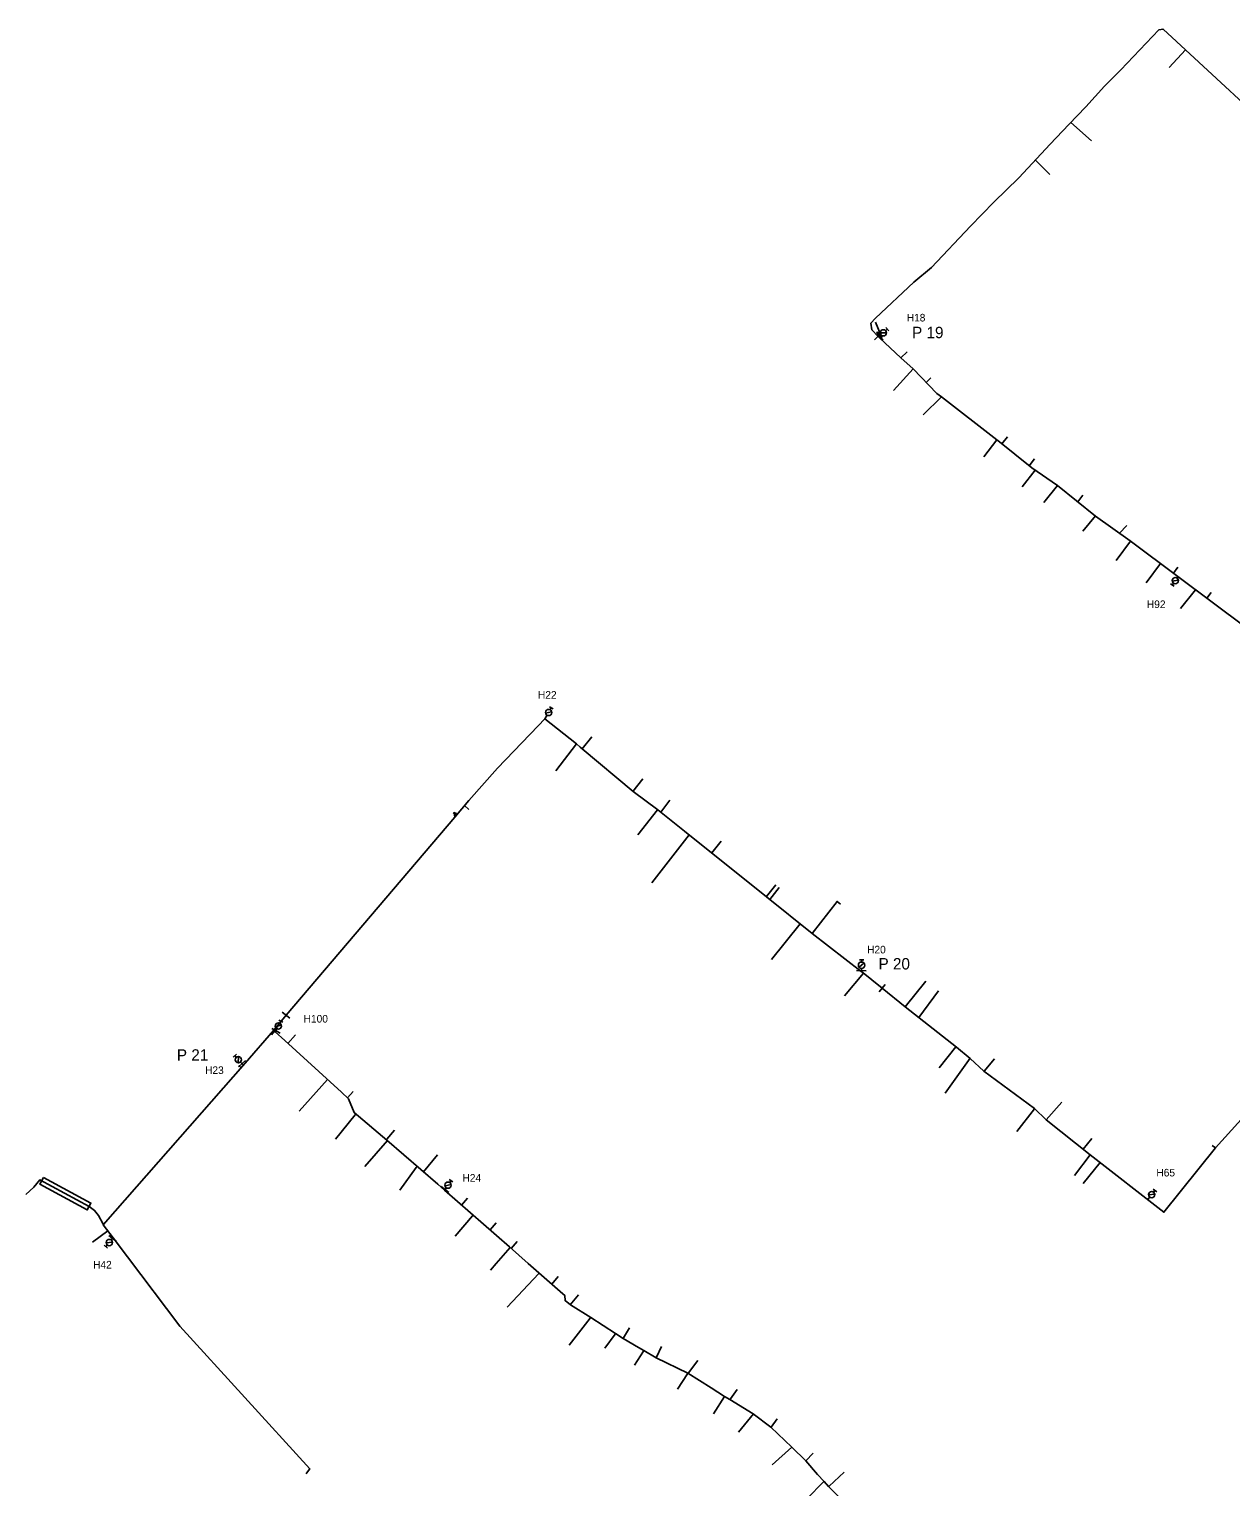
# Model space of a CAD drawing. Extents: x -548873 to -538270, y -1201997 to -1192514.
# Drawn here: x -547630.3 to -547314.4, y -1195490.5 to -1195107.4 of the extents above; entities that cross this region are included whole.
import ezdxf

# ---------------------------------------------------------------- set-up
doc = ezdxf.new("R2010")
doc.units = 0
for name, color, linetype in [('KN_HRAN_STÁTNÍ', 7, 'Continuous'), ('KN_PARC_Č', 7, 'Continuous'), ('KN_VKP_HRAN_SPORNÁ', 7, 'Continuous'), ('PK_PARC_Čv', 7, 'Continuous'), ('Vrstva 29', 7, 'Continuous'), ('Vrstva 37', 7, 'Continuous'), ('Vrstva 39', 7, 'Continuous')]:
    doc.layers.add(name, color=color, linetype=linetype)

# ---------------------------------------------------------------- blocks, each defined once
blk = doc.blocks.new('147')
at = {"layer": 'KN_HRAN_STÁTNÍ'}
blk.add_line((0, 1.27), (0, -1.27), dxfattribs=at)
blk = doc.blocks.new('160')
at = {"layer": 'KN_HRAN_STÁTNÍ'}
blk.add_circle((0, 0), 0.0458, dxfattribs=at)
blk = doc.blocks.new('133')
at = {"layer": 'KN_HRAN_STÁTNÍ'}
for p, q in [((0.28, 0), (0, 0)), ((0.54, 0.58), (1.7, -0.58)), ((1.94, 0), (2.52, 0)), ((2.52, 0.58), (2.52, -0.58))]:
    blk.add_line(p, q, dxfattribs=at)
blk.add_circle((1.11, 0), 0.825, dxfattribs=at)
blk = doc.blocks.new('150')
at = {"layer": 'KN_HRAN_STÁTNÍ'}
blk.add_line((0, 1.27), (0, -1.27), dxfattribs=at)
blk = doc.blocks.new('128')
at = {"layer": 'KN_HRAN_STÁTNÍ'}
for p, q in [((-0.19, 1.06), (-0.43, 1.15)), ((-0.36, 0.84), (-0.19, 1.06)), ((-0.19, 1.06), (-0.02, 1.25)), ((-0.19, 1.06), (0, 0)), ((0.05, 0.95), (-0.19, 1.06)), ((-0.1, 1), (0.41, 0.91)), ((-0.07, 0.82), (0.17, 0.96)), ((0.17, 0.96), (-0.02, 1.13)), ((0.17, 0.96), (0, 0)), ((0.19, 1.21), (0.17, 0.96)), ((0.17, 0.96), (0.38, 1.08)), ((0.36, 0.77), (0.17, 0.96))]:
    blk.add_line(p, q, dxfattribs=at)

msp = doc.modelspace()

# ---------------------------------------------------------------- linework, layer by layer
at = {"layer": 'KN_PARC_Č'}
for points in [[(-547326.381, -1195112.848), (-547330.603, -1195117.527)], [(-547356.485, -1195131.963), (-547351.024, -1195136.804)], [(-547365.802, -1195141.849), (-547362.026, -1195145.627)], [(-547406.503, -1195188.856), (-547406.204, -1195188.492), (-547407.816, -1195184.471)], [(-547401.169, -1195193.786), (-547399.552, -1195192.239)], [(-547397.94, -1195196.725), (-547403.117, -1195202.407)], [(-547394.499, -1195200.278), (-547393.258, -1195199.076)], [(-547390.528, -1195204.113), (-547395.281, -1195208.834)], [(-547374.589, -1195216.412), (-547373.141, -1195214.62)], [(-547375.92, -1195215.349), (-547379.378, -1195219.882)], [(-547367.442, -1195222.166), (-547366.066, -1195220.38)], [(-547365.896, -1195223.313), (-547369.293, -1195227.711)], [(-547360.023, -1195227.352), (-547363.601, -1195231.869)], [(-547354.654, -1195231.656), (-547353.304, -1195229.914)], [(-547350.034, -1195235.36), (-547353.34, -1195239.37)], [(-547343.707, -1195239.893), (-547341.79, -1195237.86)], [(-547340.766, -1195242.001), (-547344.538, -1195247.058)], [(-547332.901, -1195247.876), (-547336.664, -1195252.934)], [(-547329.512, -1195250.407), (-547328.359, -1195248.873)], [(-547323.68, -1195254.763), (-547327.616, -1195259.664)], [(-547320.739, -1195256.96), (-547319.611, -1195255.461)], [(-547486.476, -1195295.298), (-547491.912, -1195302.375)], [(-547484.932, -1195296.547), (-547482.387, -1195293.385)], [(-547471.616, -1195307.744), (-547468.977, -1195304.494)], [(-547464.251, -1195313.246), (-547461.899, -1195310.091)], [(-547515.868, -1195311.487), (-547514.738, -1195312.474)], [(-547465.106, -1195312.565), (-547470.324, -1195319.21)], [(-547456.856, -1195319.155), (-547466.648, -1195331.809)], [(-547450.889, -1195323.923), (-547448.427, -1195320.847)], [(-547436.5, -1195335.421), (-547434.057, -1195332.279)], [(-547435.601, -1195336.144), (-547433.173, -1195332.992)], [(-547424.512, -1195345.067), (-547417.918, -1195336.689), (-547417.001, -1195337.424)], [(-547427.641, -1195342.55), (-547435.139, -1195351.919)], [(-547411.032, -1195355.484), (-547416.015, -1195361.46)], [(-547400.069, -1195364.357), (-547394.573, -1195357.586)], [(-547396.459, -1195367.202), (-547391.313, -1195360.133)], [(-547562.328, -1195373.977), (-547560.319, -1195371.765)], [(-547386.678, -1195374.91), (-547391.075, -1195380.4)], [(-547382.968, -1195377.872), (-547389.56, -1195387.054)], [(-547379.306, -1195381.295), (-547376.549, -1195378.035)], [(-547574.578, -1195380.387), (-547575.215, -1195379.795)], [(-547551.867, -1195383.499), (-547559.371, -1195391.76)], [(-547546.629, -1195388.267), (-547545.111, -1195386.6)], [(-547366.008, -1195391.159), (-547370.716, -1195397.158)], [(-547362.966, -1195394.05), (-547358.836, -1195389.461)], [(-547544.462, -1195392.486), (-547544.66, -1195392.72), (-547549.822, -1195399.133)], [(-547536.403, -1195399.288), (-547536.32, -1195399.19), (-547534.291, -1195396.783)], [(-547536.165, -1195399.492), (-547542.121, -1195406.33)], [(-547353.25, -1195401.75), (-547350.994, -1195398.962)], [(-547318.463, -1195401.456), (-547319.335, -1195400.785)], [(-547528.326, -1195406.29), (-547528.56, -1195406.56), (-547532.845, -1195412.576)], [(-547526.671, -1195407.725), (-547523.002, -1195403.252)], [(-547351.384, -1195403.229), (-547355.534, -1195408.716)], [(-547348.788, -1195405.252), (-547353.278, -1195410.771)], [(-547610.869, -1195421.66), (-547610.98, -1195421.31), (-547612.09, -1195419.18), (-547613.15, -1195417.89), (-547614.57, -1195416.84), (-547627.535, -1195409.873), (-547629.13, -1195411.77), (-547631.22, -1195413.65)], [(-547516.647, -1195416.456), (-547515.064, -1195414.646)], [(-547513.646, -1195419.083), (-547513.81, -1195419.27), (-547518.346, -1195424.656)], [(-547509.18, -1195422.992), (-547507.524, -1195421.099)], [(-547609.688, -1195423.198), (-547613.688, -1195426.197)], [(-547503.875, -1195427.638), (-547507.601, -1195431.825), (-547509.042, -1195433.557)], [(-547503.605, -1195427.873), (-547502.008, -1195426.055)], [(-547496.276, -1195434.292), (-547496.38, -1195434.41), (-547504.689, -1195443.293)], [(-547492.941, -1195437.212), (-547491.24, -1195435.279)], [(-547488.088, -1195442.648), (-547485.938, -1195440.03)], [(-547482.71, -1195445.99), (-547482.82, -1195446.16), (-547488.388, -1195453.293)], [(-547476.176, -1195450.213), (-547476.27, -1195450.36), (-547479.01, -1195454.066)], [(-547474.173, -1195451.492), (-547474.07, -1195451.33), (-547472.517, -1195448.761)], [(-547468.745, -1195454.669), (-547468.86, -1195454.86), (-547471.188, -1195458.544)], [(-547465.508, -1195456.611), (-547465.43, -1195456.45), (-547464.07, -1195453.643)], [(-547457.073, -1195460.707), (-547456.98, -1195460.56), (-547454.579, -1195457.337)], [(-547457.194, -1195460.633), (-547457.27, -1195460.79), (-547459.903, -1195464.825)], [(-547447.506, -1195466.75), (-547450.443, -1195471.364)], [(-547446.102, -1195467.599), (-547446, -1195467.43), (-547444.23, -1195464.911)], [(-547439.936, -1195471.338), (-547443.886, -1195476.124)], [(-547435.303, -1195474.827), (-547433.662, -1195472.665)], [(-547429.792, -1195480.118), (-547434.987, -1195484.706)], [(-547426.185, -1195483.676), (-547424.206, -1195481.664)], [(-547557.412, -1195486.959), (-547557.533, -1195487.118)], [(-547420.177, -1195490.464), (-547420.06, -1195490.36), (-547416.071, -1195486.63)], [(-547421.368, -1195489.122), (-547421.49, -1195489.23), (-547425.759, -1195493.564)]]:
    msp.add_lwpolyline(points, dxfattribs=at)
at = {"layer": 'KN_VKP_HRAN_SPORNÁ'}
for points in [[(-547407.16, -1195188.22), (-547408.78, -1195186.5), (-547409.06, -1195184.71), (-547407.87, -1195183.42), (-547397.79, -1195173.9), (-547393.14, -1195170.06), (-547382.83, -1195159.23), (-547376.73, -1195152.92), (-547370.15, -1195146.53), (-547361.93, -1195137.68), (-547356.985, -1195132.487), (-547352.54, -1195127.82), (-547347.64, -1195122.46), (-547343.34, -1195118.13), (-547333.35, -1195107.66), (-547332.24, -1195107.45), (-547322.865, -1195116.088), (-547305.38, -1195132.2)], [(-547246.367, -1195310.496), (-547269.826, -1195293.702), (-547279.585, -1195286.587), (-547286.559, -1195281.503), (-547301.829, -1195270.746), (-547306, -1195267.463), (-547310.314, -1195264.746), (-547328.316, -1195251.3), (-547340.855, -1195241.935), (-547349.979, -1195235.404), (-547360.017, -1195227.356), (-547366.721, -1195222.746), (-547375.659, -1195215.551), (-547375.928, -1195215.344), (-547390.528, -1195204.112), (-547391.692, -1195203.177), (-547397.912, -1195196.751), (-547401.169, -1195193.786), (-547406.77, -1195188.61), (-547406.97, -1195188.42), (-547407.16, -1195188.22)], [(-547406.112, -1195359.466), (-547411.551, -1195355.064), (-547411.574, -1195355.046), (-547424.447, -1195345.12), (-547436.481, -1195335.436), (-547458.035, -1195318.213), (-547465.066, -1195312.595), (-547471.58, -1195307.774), (-547484.932, -1195296.547), (-547485.465, -1195296.099), (-547486.476, -1195295.298), (-547494.772, -1195288.72), (-547496.509, -1195290.518), (-547507.239, -1195301.624), (-547514.765, -1195310.191), (-547518.433, -1195314.501)], [(-547518.433, -1195314.501), (-547562.79, -1195366.54)], [(-547240.594, -1195319.52), (-547246.61, -1195324.43), (-547256.655, -1195332.627), (-547281.532, -1195359.754), (-547289.044, -1195368.93), (-547318.463, -1195401.456), (-547332.03, -1195418.311)], [(-547332.03, -1195418.311), (-547351.377, -1195403.235), (-547362.995, -1195394.027), (-547366.048, -1195391.121), (-547379.321, -1195381.284), (-547382.913, -1195377.916), (-547386.55, -1195375.011), (-547400.044, -1195364.377), (-547406.112, -1195359.466)], [(-547562.79, -1195366.54), (-547566.09, -1195370.6)], [(-547566.09, -1195370.6), (-547573.554, -1195379.222), (-547610.869, -1195421.66)], [(-547566.09, -1195370.6), (-547565.84, -1195370.77)], [(-547565.84, -1195370.77), (-547565.62, -1195370.98), (-547563.131, -1195373.246), (-547548.208, -1195386.83), (-547546.34, -1195388.53), (-547544.86, -1195392.15), (-547536.286, -1195399.387), (-547522.878, -1195411.015), (-547521.12, -1195412.54), (-547504.083, -1195427.455), (-547499.114, -1195431.807), (-547490.02, -1195439.77), (-547489.53, -1195440.19), (-547489.44, -1195441.55), (-547488.06, -1195442.67), (-547482.71, -1195445.99), (-547476.18, -1195450.21), (-547474.16, -1195451.5), (-547470.111, -1195453.87), (-547468.76, -1195454.66), (-547465.51, -1195456.61), (-547457.18, -1195460.64), (-547451.046, -1195464.514), (-547447.49, -1195466.76), (-547446.1, -1195467.6), (-547439.96, -1195471.32), (-547435.31, -1195474.82), (-547429.79, -1195480.12), (-547426.19, -1195483.67), (-547423.042, -1195487.229), (-547421.37, -1195489.12), (-547420.18, -1195490.46), (-547414.68, -1195496.05)], [(-547610.869, -1195421.66), (-547608.249, -1195425.072), (-547604.465, -1195430.088), (-547590.73, -1195448.29)], [(-547590.73, -1195448.29), (-547556.525, -1195485.804), (-547557.412, -1195486.959)]]:
    msp.add_lwpolyline(points, dxfattribs=at)
at = {"layer": 'PK_PARC_Čv'}
for points in [[(-547406.97, -1195188.42), (-547406.72, -1195188.17), (-547406.56, -1195188.02)], [(-547328.316, -1195251.3), (-547328.42, -1195251.45)], [(-547494.772, -1195288.72), (-547494.339, -1195287.991)], [(-547411.572, -1195355.048), (-547411.549, -1195354.546)], [(-547565.62, -1195370.98), (-547565.44, -1195370.69), (-547565.3, -1195370.41)], [(-547574.007, -1195379.737), (-547574.572, -1195379.102)], [(-547521.12, -1195412.54), (-547520.98, -1195412.39), (-547520.82, -1195412.16)], [(-547336.253, -1195415.021), (-547335.914, -1195414.598)], [(-547608.249, -1195425.072), (-547608.376, -1195425.226), (-547608.562, -1195425.452)]]:
    msp.add_lwpolyline(points, dxfattribs=at)
at = {"layer": 'Vrstva 37'}
msp.add_lwpolyline([(-547626.569, -1195409.257), (-547614.097, -1195415.959), (-547615.043, -1195417.721), (-547627.515, -1195411.019), (-547626.569, -1195409.257)], dxfattribs=at)

# ---------------------------------------------------------------- block references
at = {"layer": 'PK_PARC_Čv'}
for name, p, xscale, yscale, rotation in [('150', (-547406.72, -1195188.17), 0.999999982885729, 0.9999999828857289, 45), ('133', (-547406.56, -1195188.02), 1.0000000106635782, 1.0000000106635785, 44.00000165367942), ('133', (-547328.42, -1195251.45), 0.9999999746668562, 0.999999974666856, -124.00000045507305), ('133', (-547494.339, -1195287.991), 0.9999999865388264, 0.9999999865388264, 59.99999955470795), ('133', (-547411.549, -1195354.546), 1.00000001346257, 1.0000000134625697, 88.00000009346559), ('150', (-547411.563, -1195354.848), 1.00000001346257, 1.0000000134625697, 88.00000009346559), ('133', (-547565.3, -1195370.41), 1.0000000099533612, 1.0000000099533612, 63.999999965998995), ('150', (-547565.44, -1195370.69), 1.0000000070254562, 1.0000000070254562, 61.000001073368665), ('133', (-547574.572, -1195379.102), 1.0000000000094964, 1.0000000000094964, 132.0000013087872), ('150', (-547574.393, -1195379.303), 1.0000000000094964, 1.0000000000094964, -47.99999869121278), ('133', (-547520.82, -1195412.16), 0.9999999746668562, 0.999999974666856, 55.999999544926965), ('150', (-547520.98, -1195412.39), 1.000000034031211, 1.0000000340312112, 51.999999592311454), ('133', (-547335.914, -1195414.598), 1.000000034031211, 1.0000000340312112, 51.999999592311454), ('133', (-547608.562, -1195425.452), 1.000000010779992, 1.0000000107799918, -128.99999891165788), ('150', (-547608.376, -1195425.226), 1.000000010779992, 1.0000000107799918, 51.00000108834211)]:
    msp.add_blockref(name, p, dxfattribs=dict(at, xscale=xscale, yscale=yscale, rotation=rotation))
at = {"layer": 'Vrstva 29'}
for name, p, xscale, yscale, rotation in [('147', (-547407.16, -1195188.22), 1.0000000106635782, 1.0000000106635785, 134.00000165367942), ('160', (-547518.433, -1195314.501), 1.0000000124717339, 1.0000000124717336, 49.99999868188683), ('147', (-547406.112, -1195359.466), 1.000000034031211, 1.0000000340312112, 141.99999959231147), ('147', (-547562.79, -1195366.54), 1.000000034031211, 1.0000000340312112, -128.00000040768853), ('147', (-547565.84, -1195370.77), 1.000000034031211, 1.0000000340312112, -38.000000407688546), ('160', (-547566.09, -1195370.6), 1.000000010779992, 1.0000000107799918, 51.00000108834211), ('160', (-547610.869, -1195421.66), 1.000000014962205, 1.0000000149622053, -90.99999994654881), ('160', (-547332.03, -1195418.311), 1.0098116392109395, 1.0098116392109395, -169.38969821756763), ('160', (-547590.73, -1195448.29), 1.0000000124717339, 1.0000000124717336, 130.0000013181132), ('160', (-547557.412, -1195486.959), 0.9999999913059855, 0.9999999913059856, -127.00000193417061)]:
    msp.add_blockref(name, p, dxfattribs=dict(at, xscale=xscale, yscale=yscale, rotation=rotation))
at = {"layer": 'Vrstva 39'}
for p in [(-547407.16, -1195188.22), (-547518.433, -1195314.501)]:
    msp.add_blockref('128', p, dxfattribs=at)

# ---------------------------------------------------------------- texts
at = {"layer": 'PK_PARC_Čv'}
for s, height, p in [('H18', 2, (-547399.63, -1195184.27)), ('P 19', 3, (-547398.22, -1195188.66)), ('H92', 2, (-547336.5, -1195259.58)), ('H22', 2, (-547496.569, -1195283.391)), ('H20', 2, (-547410.049, -1195350.336)), ('P 20', 3, (-547407.039, -1195354.556)), ('H100', 2, (-547558.18, -1195368.51)), ('P 21', 3, (-547591.492, -1195378.532)), ('H23', 2, (-547584.082, -1195382.022)), ('H24', 2, (-547516.42, -1195410.33)), ('H65', 2, (-547334.004, -1195408.948)), ('H42', 2, (-547613.522, -1195433.142))]:
    msp.add_text(s, height=height, dxfattribs=at).set_placement(p)

doc.saveas('drawing.dxf')
